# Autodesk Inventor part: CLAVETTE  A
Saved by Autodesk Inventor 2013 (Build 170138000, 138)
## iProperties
Created: 2012-12
Part Number: CLAVETTE  A
Material: Générique
Document SubType Name: Modeling
Designer: jost thierry
Density: 1 g/cm^3
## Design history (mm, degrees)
node "CLAVETTE  A1"
node "CLAVETTE  A"
node "Base1"
